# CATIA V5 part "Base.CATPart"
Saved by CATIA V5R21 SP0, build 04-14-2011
Part number: Base
Bounding box of the stored display mesh (mm): x -23.876 to 23.876, y 0 to 88.9, z 0 to 54.102
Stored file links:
  D:\CATIA V5R21 E-RESOURCES\CATIA-V5R21\catia-v5r21-Prts\c13_catia_v5r21_prt\c13_catia_v5r21_figr_13-43\Part & Asm files\Base.CATPart
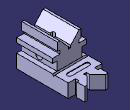
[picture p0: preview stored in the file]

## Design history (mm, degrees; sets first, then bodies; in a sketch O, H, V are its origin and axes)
Body1 (main body)
  Sketch1 on xy-plane, origin (0, 0, 0), H (1, 0, 0), V (0, 1, 0)
    line L1 (-23.876, 0) -> (23.876, 0)
    point P1 (-23.876, 0)
    point P2 (23.876, 0)
    construction line L2 (-23.876, 50.8) -> (23.876, 50.8)
    point P3 (-23.876, 50.8)
    point P4 (23.876, 50.8)
    line L3 (23.876, 0) -> (23.876, 72.898)
    point P5 (23.876, 72.898)
    line L4 (23.876, 72.898) -> (13.462, 72.898)
    point P6 (13.462, 72.898)
    line L5 (13.462, 72.898) -> (13.462, 77.724)
    point P7 (13.462, 77.724)
    line L6 (13.462, 77.724) -> (16.51, 77.724)
    point P8 (16.51, 77.724)
    line L7 (16.51, 77.724) -> (16.51, 88.9)
    point P9 (16.51, 88.9)
    line L8 (16.51, 88.9) -> (13.462, 88.9)
    point P10 (13.462, 88.9)
    line L9 (13.462, 88.9) -> (1.778, 77.724)
    point P11 (1.778, 77.724)
    line L10 (1.778, 77.724) -> (1.778, 72.898)
    point P12 (1.778, 72.898)
    line L11 (1.778, 72.898) -> (0, 72.898)
    point P13 (0, 72.898)
    point P14 (0, 72.898)
    point P15 (-1.778, 72.898)
    line L12 (-1.778, 72.898) -> (0, 72.898)
    point P16 (-1.778, 77.724)
    line L13 (-1.778, 77.724) -> (-1.778, 72.898)
    point P17 (-13.462, 88.9)
    line L14 (-13.462, 88.9) -> (-1.778, 77.724)
    point P18 (-16.51, 88.9)
    line L15 (-16.51, 88.9) -> (-13.462, 88.9)
    point P19 (-16.51, 77.724)
    line L16 (-16.51, 77.724) -> (-16.51, 88.9)
    point P20 (-13.462, 77.724)
    line L17 (-13.462, 77.724) -> (-16.51, 77.724)
    point P21 (-13.462, 72.898)
    line L18 (-13.462, 72.898) -> (-13.462, 77.724)
    point P22 (-23.876, 72.898)
    line L19 (-23.876, 72.898) -> (-13.462, 72.898)
    point P23 (-23.876, 50.8)
    point P24 (23.876, 50.8)
    construction line L20 (23.876, 50.8) -> (-23.876, 50.8)
    point P25 (-23.876, 0)
    line L21 (-23.876, 0) -> (-23.876, 72.898)
    length L1 = 47.752
    distance P2 V = 23.876
    distance L2 L1 = 50.8
    distance P5 L2 = 22.098
    distance L7 P1 = 40.386
    distance L5 P1 = 37.338
    distance L2 P7 = 26.924
    distance P9 L2 = 38.1
    distance P10 L3 = 10.414
    distance L10 L3 = 22.098
    distance L11 L2 = 22.098
    distance P11 L2 = 26.924
    horizontal: L1 H, L2 H, L4 H, L6 H, L8 H, L11 H
    coincidence: H L1, P13 V, P13 P14
    vertical: L3 V, L5 V, L7 V, L10 V
    symmetry: P13 P14 V, P12 P15 V, L11 L12 V, P11 P16 V, L10 L13 V, P10 P17 V, L9 L14 V, P9 P18 V, L8 L15 V, P8 P19 V, L7 L16 V, P7 P20 V, L6 L17 V, P6 P21 V, L5 L18 V, P5 P22 V, L4 L19 V, P4 P23 V, P3 P24 V, L2 L20 V, P2 P25 V, L3 L21 V
  Pad1: profile Sketch1, direction (0, 0, 1), length 19.05
  Sketch2 on face of Pad1, origin (23.876, 0, 0), H (0, 1, 0), V (0, 0, 1)
    point P1 (50.8, 19.05)
    line L1 (50.8, 19.05) -> (52.324, 16.4104)
    line L2 (52.324, 16.4104) -> (53.848, 19.05)
    line L3 (53.848, 19.05) -> (50.8, 19.05)
    reference projected line E1 (72.898, 19.05) -> (0, 19.05) from edge of Pad1
    length L2 = 3.048
    length L1 = 3.048
    distance P1 V = 50.8
    angle L1 L2 = 60
    horizontal: L3 H
    coincidence: L3 E1
  Pocket1: profile Sketch2, direction (-1, 0, 0), through (limit type 6)
  Sketch3 on face of Pad1, origin (0, 0, 0), H (1, 0, 0), V (0, 0, 1)
    line L1 (17.526, 19.05) -> (17.526, 31.75)
    point P1 (17.526, 19.05)
    point P2 (17.526, 31.75)
    line L2 (17.526, 31.75) -> (23.876, 31.75)
    point P3 (23.876, 31.75)
    line L3 (23.876, 31.75) -> (23.876, 38.1)
    point P4 (23.876, 38.1)
    line L4 (23.876, 38.1) -> (13.462, 38.1)
    point P5 (13.462, 38.1)
    line L5 (13.462, 38.1) -> (13.462, 42.926)
    point P6 (13.462, 42.926)
    line L6 (13.462, 42.926) -> (16.637, 42.926)
    point P7 (16.637, 42.926)
    line L7 (16.637, 42.926) -> (16.637, 54.102)
    point P8 (16.637, 54.102)
    reference projected line E1 (23.876, 19.05) -> (-23.876, 19.05) from edge of Pad1
    reference projected line E2 (23.876, 0) -> (23.876, 19.05) from edge of Pad1
    reference projected line E3 (-23.876, 19.05) -> (-23.876, 0) from edge of Pad1
    line L8 (16.637, 54.102) -> (13.462, 54.102)
    point P9 (13.462, 54.102)
    point P10 (1.651, 41.402)
    line L9 (1.651, 41.402) -> (1.651, 38.1)
    point P11 (1.651, 38.1)
    line L10 (1.651, 38.1) -> (0, 38.1)
    point P12 (0, 38.1)
    line L11 (1.651, 41.402) -> (13.462, 54.102)
    point P13 (-13.462, 54.102)
    point P14 (-1.651, 41.402)
    line L12 (-1.651, 41.402) -> (-13.462, 54.102)
    point P15 (0, 38.1)
    point P16 (-1.651, 38.1)
    line L13 (-1.651, 38.1) -> (0, 38.1)
    line L14 (-1.651, 41.402) -> (-1.651, 38.1)
    point P17 (-16.637, 54.102)
    line L15 (-16.637, 54.102) -> (-13.462, 54.102)
    point P18 (-16.637, 42.926)
    line L16 (-16.637, 42.926) -> (-16.637, 54.102)
    point P19 (-13.462, 42.926)
    line L17 (-13.462, 42.926) -> (-16.637, 42.926)
    point P20 (-13.462, 38.1)
    line L18 (-13.462, 38.1) -> (-13.462, 42.926)
    point P21 (-23.876, 38.1)
    line L19 (-23.876, 38.1) -> (-13.462, 38.1)
    point P22 (-23.876, 31.75)
    line L20 (-23.876, 31.75) -> (-23.876, 38.1)
    point P23 (-17.526, 31.75)
    line L21 (-17.526, 31.75) -> (-23.876, 31.75)
    point P24 (-17.526, 19.05)
    line L22 (-17.526, 19.05) -> (-17.526, 31.75)
    line L23 (-17.526, 19.05) -> (17.526, 19.05)
    distance V L1 = 17.526
    distance L2 H = 31.75
    distance L4 H = 38.1
    distance L6 H = 42.926
    distance L7 V = 16.637
    distance L5 E3 = 37.338
    distance V P9 = 13.462
    distance L8 H = 54.102
    distance L9 V = 1.651
    length L9 = 3.302
    vertical: L1 V, L3 V, L5 V, L7 V, L9 V
    horizontal: L2 H, L4 H, L6 H, L8 H, L10 H, L23 H
    coincidence: P1 E1, L3 E2, P11 L4, P12 V, P12 P15
    symmetry: P9 P13 V, P10 P14 V, L11 L12 V, P12 P15 V, P11 P16 V, L10 L13 V, L9 L14 V, P8 P17 V, L8 L15 V, P7 P18 V, L7 L16 V, P6 P19 V, L6 L17 V, P5 P20 V, L5 L18 V, P4 P21 V, L4 L19 V, P3 P22 V, L3 L20 V, P2 P23 V, L2 L21 V, P1 P24 V, L1 L22 V
  Pad2: profile Sketch3, direction (0, 1, 0), length 50.8
  Sketch4 on face of Pad1, origin (4.0235, 27.8102, 0), H (1, 0, 0), V (0, -1, 0)
    point P1 (-4.0235, 2.4102)
    reference projected line E1 (13.5025, -22.9898) -> (-21.5495, -22.9898) from edge of Pad2
    reference intersected line E2 through (-4.0235, 0) direction (0, 1) from yz-plane
    distance P1 E1 = 25.4
    coincidence: E2 P1
  Hole1: placed by Sketch4, at (0, 25.4, 0) direction (0, 0, 1), diameter 7.874, depth 54.102
  Sketch5 on face of Pad2, origin (17.526, 12.3932, 23.5222), H (0, 1, 0), V (0, 0, 1)
    point P1 (13.0068, 1.8778)
    reference projected line E1 (-12.3932, 8.2278) -> (-12.3932, -4.4722) from edge of Pad2
    reference projected line E2 (-12.3932, -23.5222) -> (60.5048, -23.5222) from edge of Pad1
    distance E1 P1 = 25.4
    distance E2 P1 = 25.4
  Hole2: placed by Sketch5, at (17.526, 25.4, 25.4) direction (-1, 0, 0), diameter 9.652, depth 54.102
  Sketch6 on face of Pad1, origin (0, 0, 19.05), H (1, 0, 0), V (0, 1, 0)
    construction line L1 (-23.876, 63.373) -> (23.876, 63.373)
    point P1 (-23.876, 63.373)
    point P2 (23.876, 63.373)
    reference projected line E1 (23.876, 53.848) -> (-23.876, 53.848) from edge of Pocket1
    construction line L2 (-12.7, 63.373) -> (12.7, 63.373)
    point P3 (-12.7, 63.373)
    line L3 (-12.7, 66.548) -> (12.7, 66.548)
    line L4 (12.7, 60.198) -> (-12.7, 60.198)
    arc A1 centre (12.7, 63.373) radius 3.175 from (12.7, 66.548) to (12.7, 60.198) cw
    arc A2 centre (-12.7, 63.373) radius 3.175 from (-12.7, 60.198) to (-12.7, 66.548) cw
    reference projected line E2 (23.876, 72.898) -> (23.876, 0) from edge of Pad1
    reference projected line E3 (-23.876, 72.898) -> (-23.876, 0) from edge of Pad1
    reference projected line E4 (-23.876, 72.898) -> (-23.876, 0) from edge of Pad1
    distance E1 L1 = 9.525
    radius A1 = 3.175
    distance A1 A2 = 31.75
    distance P3 E4 = 11.176
    horizontal: L1 H, L2 H
    coincidence: P3 L1, P2 E2, P1 E3
    tangency: A1 L3, A2 L3, A1 L4, A2 L4
    parallelism: L2 L3
  Pocket2: profile Sketch6, direction (0, 0, -1), length 0.762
